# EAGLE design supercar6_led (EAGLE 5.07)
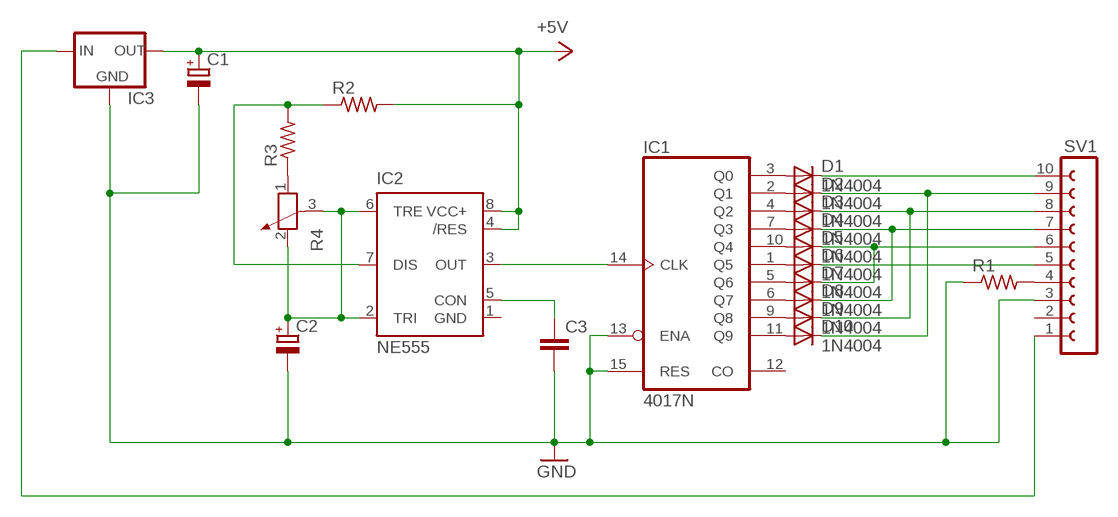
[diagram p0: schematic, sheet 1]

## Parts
C1  CPOL-EUE2.5-7  [E2,5-7]
C2  CPOL-EUE2.5-7  [E2,5-7]
C3  C-EU050-025X075  [C050-025X075]
D1  1N4004  [DO41-10]
D2  1N4004  [DO41-10]
D3  1N4004  [DO41-10]
D4  1N4004  [DO41-10]
D5  1N4004  [DO41-10]
D6  1N4004  [DO41-10]
D7  1N4004  [DO41-10]
D8  1N4004  [DO41-10]
D9  1N4004  [DO41-10]
D10  1N4004  [DO41-10]
IC1  4017N  [DIL16]
IC2  NE555  [DIL-08]
IC3  78XXS  [78XXS]
R1  R-US_0207/10  [0207/10]
R2  R-US_0207/10  [0207/10]
R3  R-US_0207/10  [0207/10]
R4  POTENTIOMETER_PT-10S  [PT-10S]
SV1  FE10-1  [FE10]

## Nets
N$1: D1.A IC1.3(Q0)
N$2: D2.A IC1.2(Q1)
N$3: D3.A IC1.4(Q2)
N$4: D4.A IC1.7(Q3)
N$5: D5.A IC1.10(Q4)
N$6: D6.A IC1.1(Q5)
N$7: D7.A IC1.5(Q6)
N$8: D8.A IC1.6(Q7)
N$9: D9.A IC1.9(Q8)
N$10: D10.A IC1.11(Q9)
N$11: C2.+ IC2.2(TRI) IC2.6(TRE) R4.2 R4.3
N$12: R3.1 R4.1
N$13: IC2.7(DIS) R2.1 R3.2
N$14: D1.C SV1.10
N$17: IC1.14(CLK) IC2.3(OUT)
N$18: D2.C D10.C SV1.9
N$19: C3.1 IC2.5(CON)
N$20: D3.C D9.C SV1.8
N$21: D4.C D8.C SV1.7
N$22: D5.C D7.C SV1.6
N$23: D6.C SV1.5
N$28: R1.2 SV1.4
N$33: IC3.IN SV1.1
VDD: C1.+ IC2.4(/RES) IC2.8(VCC+) IC3.OUT R2.2 ; supply symbol labelled +5V
VSS: C1.- C2.- C3.2 IC1.13(ENA) IC1.15(RES) IC3.GND R1.1 SV1.3 ; supply symbol labelled GND
Unconnected: IC1.12(CO) SV1.2

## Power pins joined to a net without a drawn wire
VDD: IC1.16(VDD)
VSS: IC1.8(VSS) IC2.1(GND)

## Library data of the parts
C1 C2 = resistor:CPOL-EU: POLARIZED CAPACITOR, European symbol
C3 = resistor:C-EU: CAPACITOR, European symbol
D1-D10 = diode:1N4004: DIODE
IC1 = 40xx:4017: COUNTER/DIVIDER
IC2 = st-microelectronics:NE555: General purpose bipolar Timer
IC3 = v-reg:78XXS: VOLTAGE REGULATOR
R1-R3 = resistor:R-US_: RESISTOR, American symbol
R4 = rcl:POTENTIOMETER_: Potentiometer
SV1 = con-lsta:FE10-1: FEMALE HEADER

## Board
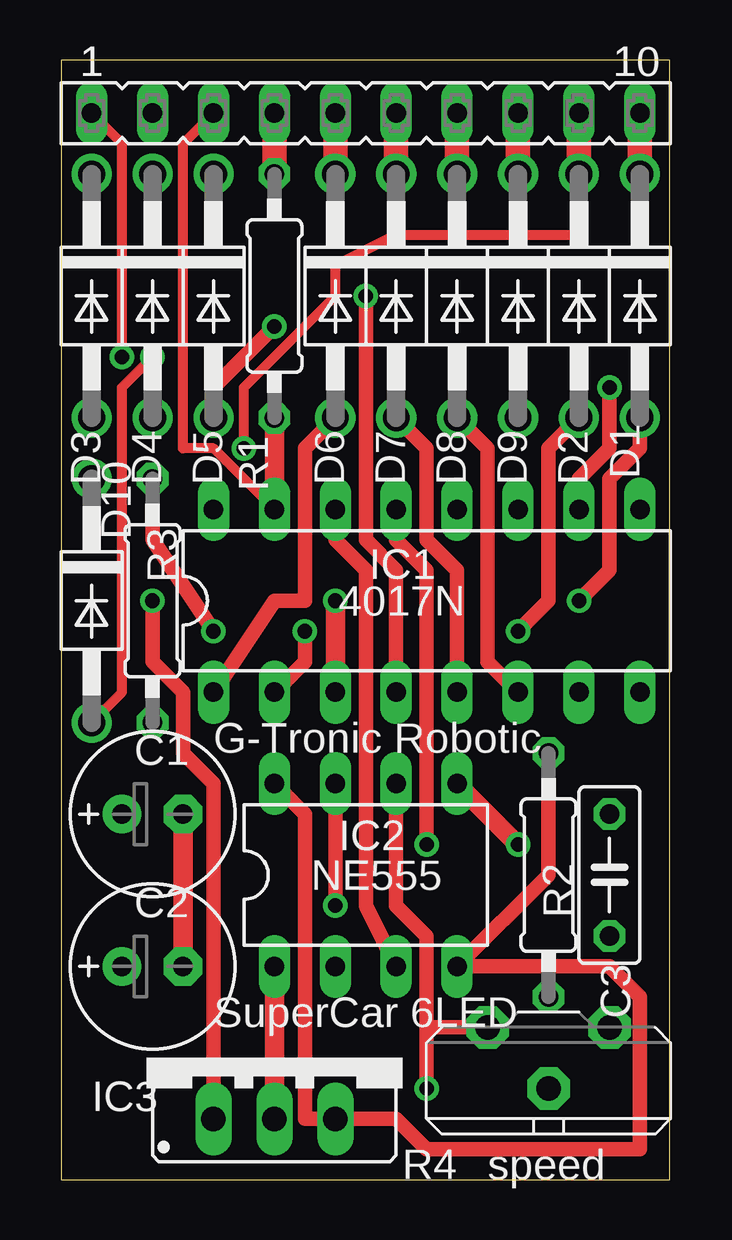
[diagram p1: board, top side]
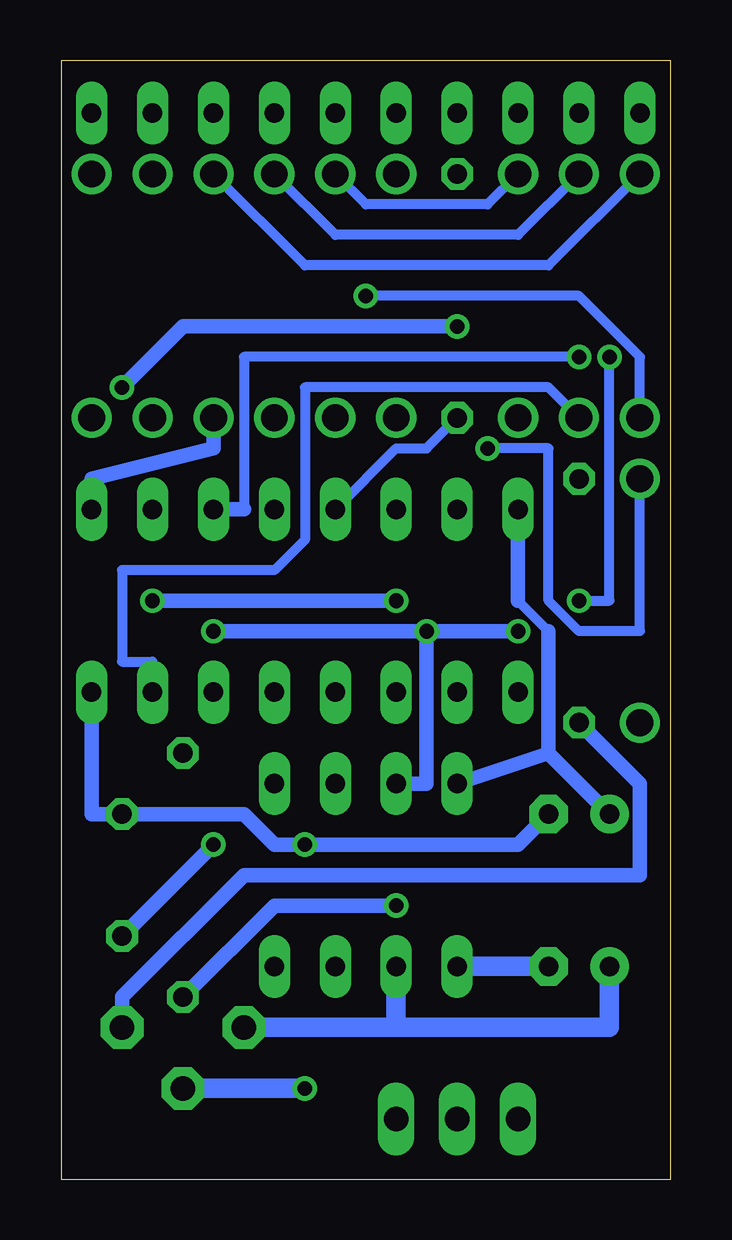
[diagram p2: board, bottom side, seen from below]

Size 25.38 x 46.66 mm. Coordinates in mm from the lower left corner, seen from the top.
Outline: 0,0 25.38,0 25.38,46.66 0,46.66 0,0
Copper layers (1*16): Top 0.035mm / dielectric 1.5mm / Bottom 0.035mm
Design rules "default": minimum track width 10mil, minimum drill 24mil, track to track 8mil, track to pad 8mil, pad to pad 8mil, via to via 8mil, smd to smd 8mil, copper to edge 40mil, drill to drill 8mil, minimum pad ring 10mil, minimum via ring 8mil, stop-mask expansion 4mil, vias tented up to drill 0mil, thermal gap 10mil

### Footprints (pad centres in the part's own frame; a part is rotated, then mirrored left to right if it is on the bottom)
E2,5-7 = drill 0.813 pad 1.6 round: + -1.27,0 | drill 0.813 pad 1.6 octagon: - 1.27,0
C050-025X075 = drill 0.813 octagon: 1 -2.54,0; 2 2.54,0
DO41-10 = drill 1.118 round: A 5.08,0; C -5.08,0
DIL16 = drill 0.813 long: 1 -8.89,-3.81; 2 -6.35,-3.81; 3 -3.81,-3.81; 4 -1.27,-3.81; 5 1.27,-3.81; 6 3.81,-3.81; 7 6.35,-3.81; 8 8.89,-3.81; 9 8.89,3.81; 10 6.35,3.81; 11 3.81,3.81; 12 1.27,3.81; 13 -1.27,3.81; 14 -3.81,3.81; 15 -6.35,3.81; 16 -8.89,3.81
DIL-08 = drill 0.813 long: 1 -3.81,-3.81; 2 -1.27,-3.81; 3 1.27,-3.81; 4 3.81,-3.81; 5 3.81,3.81; 6 1.27,3.81; 7 -1.27,3.81; 8 -3.81,3.81
78XXS = drill 1.016 long: GND 0,-2.54; IN -2.54,-2.54; OUT 2.54,-2.54
0207/10 = drill 0.813 octagon: 1 -5.08,0; 2 5.08,0
PT-10S = drill 1.016 pad 1.778 octagon: 1 -2.54,-1.27; 2 2.54,-1.27; 3 0,1.27
FE10 = drill 0.813 long: 1 -11.43,0; 2 -8.89,0; 3 -6.35,0; 4 -3.81,0; 5 -1.27,0; 6 1.27,0; 7 3.81,0; 8 6.35,0; 9 8.89,0; 10 11.43,0

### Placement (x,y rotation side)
C1  3.81,15.24 0 top
C2  3.81,8.89 0 top
C3  22.86,12.7 90 top
D1  24.13,36.83 270 top
D2  21.59,36.83 270 top
D3  1.27,36.83 270 top
D4  3.81,36.83 270 top
D5  6.35,36.83 270 top
D6  11.43,36.83 270 top
D7  13.97,36.83 270 top
D8  16.51,36.83 270 top
D9  19.05,36.83 270 top
D10  1.27,24.13 270 top
IC1  15.24,24.13 0 top
IC2  12.7,12.7 0 top
IC3  8.89,5.08 0 top
R1  8.89,36.83 90 top
R2  20.32,12.7 90 top
R3  3.81,24.13 90 top
R4  20.32,5.08 180 top
SV1  12.7,44.45 0 top

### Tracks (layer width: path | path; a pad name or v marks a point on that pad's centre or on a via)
N$1  (via drill 0.61)
  Top 0.61: v21.59,24.13 22.86,25.4 22.86,29.21 24.13,30.48 D1.A
  Top 0.813: IC1.3 v11.43,24.13
  Bottom 0.61: v11.43,24.13 v21.59,24.13
N$2  (via drill 0.61)
  Top 0.61: IC1.2 10.16,21.59 v10.16,22.86 | v19.05,22.86 20.32,24.13 20.32,30.48 D2.A
  Bottom 0.61: v10.16,22.86 v19.05,22.86
N$3  (via drill 0.61)
  Top 0.61: IC1.4 13.97,25.4 12.7,26.67 v12.7,36.83
  Bottom 0.406: v12.7,36.83 3.81,36.83 1.27,34.29 D3.A
N$4
  Bottom 0.406: IC1.7 21.59,21.59 22.86,21.59 22.86,25.4 16.51,25.4 15.24,26.67 15.24,33.02 5.08,33.02 D4.A
N$5  (via drill 0.61)
  Top 0.61: IC1.10 21.59,29.21 22.86,30.48 v22.86,33.02 | v8.89,35.56 6.35,33.02 D5.A
  Bottom 0.61: v22.86,33.02 20.32,35.56 v8.89,35.56
N$6
  Top 0.61: IC1.1 8.89,24.13 10.16,24.13 10.16,30.48 D6.A
N$7
  Top 0.61: IC1.5 16.51,25.4 15.24,26.67 15.24,30.48 D7.A
N$8
  Top 0.61: IC1.6 17.78,21.59 17.78,30.48 D8.A
N$9
  Bottom 0.61: IC1.9 24.13,29.21 19.05,30.48 D9.A
N$10  (via drill 0.61)
  Top 0.406: v3.81,34.29 2.54,33.02 2.54,20.32 D10.A
  Bottom 0.406: 17.78,27.94 17.78,34.29 v3.81,34.29
  Bottom 0.61: 17.78,27.94 IC1.11
N$11  (via drill 0.61)
  Top 0.61: IC2.6 13.97,11.43 15.24,10.16 15.24,6.35 | 15.24,6.35 v15.24,3.81 | R4.2 15.24,6.35
  Bottom 0.813: v15.24,3.81 R4.3 | 11.43,6.35 IC2.2 | 11.43,6.35 R4.2 | C2.+ 2.54,6.35 11.43,6.35
N$12
  Bottom 0.61: R3.1 1.27,16.51 1.27,12.7 17.78,12.7 22.86,7.62 R4.1
N$13  (via drill 0.61)
  Top 0.61: v11.43,11.43 IC2.7 | v6.35,22.86 3.81,26.67 R3.2
  Bottom 0.61: v11.43,11.43 16.51,11.43 R2.1 | v6.35,22.86 10.16,22.86 10.16,16.51 IC2.7
N$14
  Top 1.016: D1.C SV1.10
N$17
  Top 0.61: IC2.3 12.7,11.43 12.7,25.4 11.43,26.67 IC1.14
N$18  (via drill 0.61)
  Top 0.406: v7.62,30.48 7.62,33.02 11.43,36.83 11.43,38.1 13.97,39.37 21.59,39.37 D2.C
  Top 1.016: D2.C SV1.9
  Bottom 0.406: D10.C 1.27,22.86 3.81,22.86 5.08,24.13 5.08,30.48 v7.62,30.48
N$19  (via drill 0.61)
  Top 0.813: v19.05,13.97 IC2.5
  Bottom 0.61: C3.1 v19.05,13.97
N$20
  Top 1.016: D9.C SV1.8
  Bottom 0.406: D3.C 5.08,38.1 15.24,38.1 D9.C
N$21
  Top 1.016: D8.C SV1.7
  Bottom 0.406: D4.C 6.35,39.37 13.97,39.37 D8.C
N$22
  Top 1.016: D7.C SV1.6
  Bottom 0.406: D5.C 7.62,40.64 12.7,40.64 D7.C
N$23
  Top 1.016: D6.C SV1.5
N$28
  Top 1.016: R1.2 SV1.4
N$33  (via drill 0.61)
  Top 0.406: SV1.1 2.54,43.18 v2.54,34.29
  Top 0.61: v3.81,24.13 3.81,21.59 5.08,20.32 5.08,17.78 6.35,16.51 IC3.IN
  Bottom 0.406: v2.54,34.29 2.54,24.13 v3.81,24.13
VDD
  Top 0.61: R2.2 20.32,12.7 IC2.4 22.86,8.89 24.13,7.62 24.13,1.27 15.24,1.27 13.97,2.54 IC3.OUT 10.16,2.54 10.16,15.24 IC2.8
  Bottom 0.406: 5.08,22.86 6.35,24.13
  Bottom 0.61: 5.08,17.78 C1.+ | IC2.8 5.08,17.78 | 5.08,17.78 5.08,22.86 | 6.35,24.13 IC1.16
VSS  (via drill 0.61)
  Top 0.406: SV1.3 5.08,43.18 5.08,30.48 6.35,30.48 IC1.15
  Top 0.61: IC1.13 13.97,26.67 15.24,25.4 v15.24,13.97
  Top 0.813: R1.1 IC1.15 | C2.- C1.- | IC2.1 IC3.GND
  Bottom 0.406: IC1.13 11.43,30.48 10.16,30.48 R1.1
  Bottom 0.61: IC1.8 24.13,15.24 C3.2 17.78,15.24 16.51,13.97 v15.24,13.97 6.35,13.97 C1.-
  Bottom 0.813: C2.- IC2.1

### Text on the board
tNames: D1 | G-Tronic Robotic | SuperCar 6LED | speed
